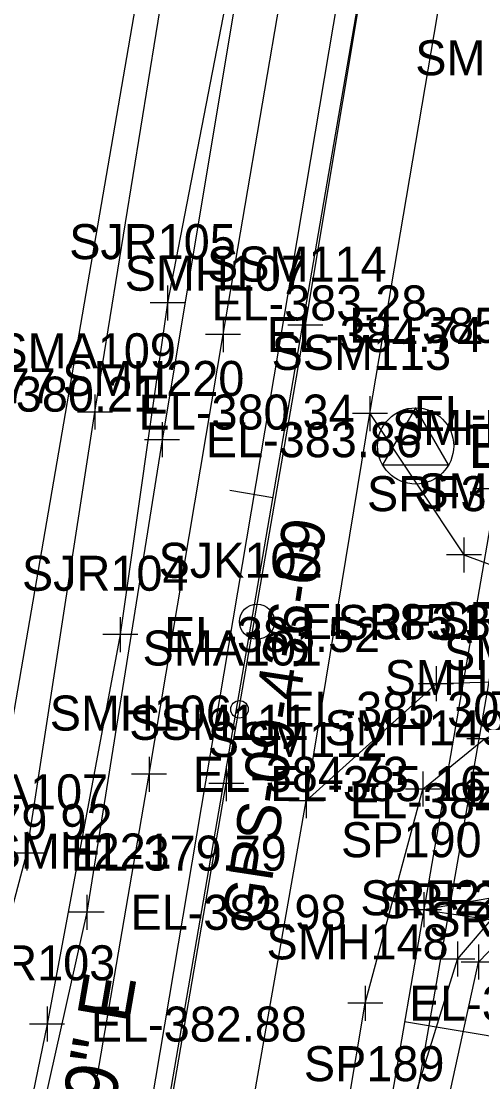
# Model space of a CAD drawing. Extents: x 1189978 to 1314812, y 571533 to 629339.
# Drawn here: x 1217440.8 to 1217493.5, y 620970.5 to 621091.6 of the extents above; entities that cross this region are included whole.
import ezdxf

# ---------------------------------------------------------------- set-up
doc = ezdxf.new("R2010")
doc.units = 0
for name, color, linetype in [('SURVEY - CENTERLINE - Preliminary', 7, 'Continuous'), ('SURVEY - CENTERLINE - Preliminary Text', 7, 'Continuous'), ('SURVEY - CONTROL - Points - Elevations', 7, 'Continuous'), ('SURVEY - CONTROL with Text', 7, 'Continuous'), ('SURVEY - DRAINAGE - Area Shapes', 7, 'Continuous'), ('SURVEY - DRAINAGE - Bridge Hydraulic Data with Text', 7, 'Continuous'), ('SURVEY - DTM - Breaklines', 7, 'Continuous'), ('SURVEY - DTM - Breaklines - Points - Elevations', 7, 'Continuous'), ('SURVEY - DTM - Breaklines - Points - Locators', 7, 'Continuous'), ('SURVEY - DTM - Breaklines - Points - Numbers', 7, 'Continuous'), ('SURVEY - DTM - Spot Points - Elevations', 7, 'Continuous'), ('SURVEY - DTM - Spot Points - Locators', 7, 'Continuous'), ('SURVEY - DTM - Spot Points - Point Numbers', 7, 'Continuous'), ('SURVEY - NON-TRANSPORTATION - Features', 7, 'Continuous'), ('SURVEY - NON-TRANSPORTATION - Features - Points - Elevations', 7, 'Continuous'), ('SURVEY - NON-TRANSPORTATION - Features - Points - Numbers', 7, 'Continuous'), ('SURVEY - PROPERTY - Property Lines', 7, 'Continuous'), ('SURVEY - PROPERTY - ROW Lines', 7, 'Continuous'), ('SURVEY - PROPERTY - ROW Lines - Points - Locators', 7, 'Continuous'), ('SURVEY - PROPERTY - ROW Lines - Points - Numbers', 7, 'Continuous'), ('SURVEY - PROPERTY - ROW Lines Text', 7, 'Continuous'), ('SURVEY - PROPERTY - Station and Offset Flags', 7, 'Continuous'), ('SURVEY - TRANSPORTATION - Features', 7, 'Continuous'), ('SURVEY - TRANSPORTATION - Features - Points - Locators', 7, 'Continuous'), ('SURVEY - TRANSPORTATION - Features - Points - Numbers', 7, 'Continuous'), ('SURVEY - TRANSPORTATION - Roads', 7, 'Continuous'), ('SURVEY - TRANSPORTATION - Roads - Points - Elevations', 7, 'Continuous'), ('SURVEY - TRANSPORTATION - Roads - Points - Locators', 7, 'Continuous'), ('SURVEY - TRANSPORTATION - Roads - Points - Numbers', 7, 'Continuous'), ('SURVEY - UTILITIES - Electric (Overhead) with Text', 7, 'Continuous'), ('SURVEY - VEGETATION - Features - Points - Elevations', 7, 'Continuous'), ('SURVEY - VEGETATION - Features - Points - Locators', 7, 'Continuous'), ('SURVEY - VEGETATION - Features - Points - Numbers', 7, 'Continuous'), ('SURVEY - VEGETATION - Features with Text', 7, 'Continuous')]:
    doc.layers.add(name, color=color, linetype=linetype)

msp = doc.modelspace()

# ---------------------------------------------------------------- linework, layer by layer
at = {"layer": 'SURVEY - CENTERLINE - Preliminary'}
msp.add_line((1217410.09, 620692.28), (1217501.58, 621222.71), dxfattribs=at)
msp.add_line((1217410.09, 620692.28), (1217501.58, 621222.71), dxfattribs=at)
at = {"layer": 'SURVEY - CENTERLINE - Preliminary Text'}
msp.add_line((1217469.58, 621037.19), (1217464.65, 621038.04), dxfattribs=at)
at = {"layer": 'SURVEY - CONTROL with Text'}
for p, q in [((1217485.89, 621047.46), (1217482.12, 621040.94)), ((1217489.65, 621040.94), (1217485.89, 621047.46)), ((1217485.89, 621043.11), (1217485.89, 621043.11)), ((1217482.12, 621040.94), (1217489.65, 621040.94))]:
    msp.add_line(p, q, dxfattribs=at)
msp.add_circle((1217485.89, 621043.11), 4.35, dxfattribs=at)
at = {"layer": 'SURVEY - DRAINAGE - Area Shapes'}
msp.add_line((1217415.87, 620731.68), (1218149.36, 625079.9), dxfattribs=at)
at = {"layer": 'SURVEY - DRAINAGE - Bridge Hydraulic Data with Text'}
msp.add_line((1217496.44, 621038.22), (1217492.44, 621038.22), dxfattribs=at)
at = {"layer": 'SURVEY - DTM - Breaklines'}
for points in [[(1217387.16, 620695.14), (1217397.48, 620747.65), (1217407.02, 620809.24), (1217418.75, 620878.96), (1217427.19, 620935.15), (1217426.68, 620940.89), (1217441.48, 620996.6), (1217449.24, 621046.98), (1217458, 621101.08), (1217460.79, 621140.2), (1217471.39, 621192.44), (1217489.7, 621292.1), (1217492.93, 621335.46), (1217504.86, 621384.61), (1217513.97, 621433.22), (1217517.91, 621473.83), (1217528.68, 621518.7), (1217534.78, 621566.14), (1217543.47, 621612.64), (1217549.89, 621643.65), (1217551.17, 621685.8), (1217565.36, 621705.38)], [(1217567.58, 621678.78), (1217566.65, 621676.81), (1217561.06, 621675.09), (1217559.37, 621666.41), (1217560.08, 621650.79), (1217551.98, 621602.78), (1217540.51, 621551.93), (1217533.57, 621500.33), (1217524.41, 621453.51), (1217516.18, 621399.79), (1217505.66, 621346.61), (1217497.91, 621291.92), (1217486.51, 621241.58), (1217479.66, 621189.93), (1217471.35, 621146.03), (1217465.62, 621095.91), (1217456.92, 621043.82), (1217448.31, 620989.84), (1217436.81, 620938.63)], [(1217418.06, 620739.44), (1217427.36, 620792.56), (1217436.72, 620845.05), (1217446.22, 620900.31), (1217455.61, 620954.21), (1217464.26, 621004.54), (1217473.29, 621056.89), (1217481.83, 621108.05), (1217491.34, 621163.83), (1217500.43, 621216.55), (1217508.98, 621267.02), (1217518.36, 621323.37), (1217527.29, 621375.81), (1217536.19, 621428.97), (1217544.91, 621481.66), (1217554.38, 621538.38), (1217563.54, 621592.41), (1217571.82, 621642.48), (1217577.37, 621677.13)], [(1217472.07, 620931.34), (1217480.14, 620979.46), (1217486.73, 621003.92), (1217493.75, 621009.65), (1217500.22, 621012.51), (1217505.41, 621014.24)], [(1217481.12, 620931.16), (1217482.16, 620956.91), (1217490.66, 620984.5), (1217504.49, 621000.62), (1217508.49, 621010.32)], [(1217483.62, 620930.86), (1217487.01, 620956.46), (1217493.09, 620984.16), (1217509.63, 621001.3)]]:
    msp.add_lwpolyline(points, dxfattribs=at)
at = {"layer": 'SURVEY - DTM - Breaklines - Points - Locators'}
for p, q in [((1217473.29, 621058.89), (1217473.29, 621054.89)), ((1217475.29, 621056.89), (1217471.29, 621056.89)), ((1217449.24, 621048.98), (1217449.24, 621044.98)), ((1217451.24, 621046.98), (1217447.24, 621046.98)), ((1217456.92, 621045.82), (1217456.92, 621041.82)), ((1217458.92, 621043.82), (1217454.92, 621043.82)), ((1217495.75, 621009.65), (1217491.75, 621009.65)), ((1217464.26, 621006.54), (1217464.26, 621002.54)), ((1217486.73, 621005.92), (1217486.73, 621001.92)), ((1217466.26, 621004.54), (1217462.26, 621004.54)), ((1217488.73, 621003.92), (1217484.73, 621003.92)), ((1217441.48, 620998.6), (1217441.48, 620994.6)), ((1217443.48, 620996.6), (1217439.48, 620996.6)), ((1217448.31, 620991.84), (1217448.31, 620987.84)), ((1217450.31, 620989.84), (1217446.31, 620989.84)), ((1217490.66, 620986.5), (1217490.66, 620982.5)), ((1217493.09, 620986.16), (1217493.09, 620982.16)), ((1217492.66, 620984.5), (1217488.66, 620984.5)), ((1217495.09, 620984.16), (1217491.09, 620984.16)), ((1217480.14, 620981.46), (1217480.14, 620977.46)), ((1217482.14, 620979.46), (1217478.14, 620979.46))]:
    msp.add_line(p, q, dxfattribs=at)
at = {"layer": 'SURVEY - DTM - Spot Points - Locators'}
msp.add_circle((1217465.77, 621013.03), 1, dxfattribs=at)
at = {"layer": 'SURVEY - NON-TRANSPORTATION - Features'}
msp.add_circle((1217467.76, 621023.05), 2, dxfattribs=at)
at = {"layer": 'SURVEY - PROPERTY - Property Lines'}
msp.add_line((1217486.83, 620990.13), (1218812.31, 620794.77), dxfattribs=at)
at = {"layer": 'SURVEY - PROPERTY - ROW Lines'}
for p, q in [((1217385.46, 620696.53), (1217476.94, 621226.96)), ((1217526.21, 621218.46), (1217486.83, 620990.13)), ((1217486.83, 620990.13), (1217482.42, 620964.55))]:
    msp.add_line(p, q, dxfattribs=at)
at = {"layer": 'SURVEY - PROPERTY - ROW Lines - Points - Locators'}
for p, q in [((1217486.83, 620992.13), (1217486.83, 620988.13)), ((1217488.83, 620990.13), (1217484.83, 620990.13))]:
    msp.add_line(p, q, dxfattribs=at)
at = {"layer": 'SURVEY - PROPERTY - ROW Lines Text'}
msp.add_lwpolyline([(1217714.69, 620938.77), (1217484.63, 620977.34)], dxfattribs=at)
at = {"layer": 'SURVEY - PROPERTY - Station and Offset Flags'}
msp.add_lwpolyline([(1217577.44, 621005.94), (1217486.83, 620990.13)], dxfattribs=at)
at = {"layer": 'SURVEY - TRANSPORTATION - Features'}
for points in [[(1217480.67, 621046.8), (1217491.41, 621030.66), (1217505.9, 621025.36), (1217530.42, 621026.78)], [(1217530.42, 621026.78), (1217530.16, 621006.83), (1217516.11, 621014.28), (1217499.82, 621016.27), (1217488.23, 621015.95), (1217473.39, 621002.58)]]:
    msp.add_lwpolyline(points, dxfattribs=at)
at = {"layer": 'SURVEY - TRANSPORTATION - Features - Points - Locators'}
for p, q in [((1217491.41, 621032.66), (1217491.41, 621028.66)), ((1217493.41, 621030.66), (1217489.41, 621030.66)), ((1217488.23, 621017.95), (1217488.23, 621013.95)), ((1217490.23, 621015.95), (1217486.23, 621015.95))]:
    msp.add_line(p, q, dxfattribs=at)
at = {"layer": 'SURVEY - TRANSPORTATION - Roads'}
for points in [[(1217409.51, 620742.51), (1217418.87, 620794.59), (1217428.1, 620847.79), (1217437.4, 620901.38), (1217446.45, 620953.25), (1217455.44, 621005.6), (1217463.89, 621055.84), (1217472.9, 621108.56), (1217482.31, 621162.33), (1217491.19, 621215.01), (1217500.52, 621270.57), (1217509.55, 621324.4), (1217518.06, 621374.09), (1217518.81, 621378.64), (1217527.27, 621430.43), (1217535.85, 621480.99), (1217545.48, 621538.85), (1217553.74, 621589.36), (1217562.47, 621641.97), (1217568.75, 621678.54), (1217567.58, 621678.78)], [(1217427.25, 620738.21), (1217436.59, 620791.34), (1217445.34, 620842.59), (1217455.15, 620898.88), (1217464.25, 620950.62), (1217473.39, 621002.58), (1217480.67, 621046.8), (1217490.83, 621106.73), (1217500.22, 621160.55), (1217509.53, 621215.72), (1217518.41, 621266.5), (1217527.5, 621321.85), (1217536.34, 621374.24), (1217563.48, 621537.92), (1217572.05, 621588.6), (1217580.58, 621640.89), (1217586, 621675.75), (1217587.38, 621675.54)]]:
    msp.add_lwpolyline(points, dxfattribs=at)
at = {"layer": 'SURVEY - TRANSPORTATION - Roads - Points - Locators'}
for p, q in [((1217463.89, 621057.84), (1217463.89, 621053.84)), ((1217465.89, 621055.84), (1217461.89, 621055.84)), ((1217480.67, 621048.8), (1217480.67, 621044.8)), ((1217482.67, 621046.8), (1217478.67, 621046.8)), ((1217455.44, 621007.6), (1217455.44, 621003.6)), ((1217457.44, 621005.6), (1217453.44, 621005.6)), ((1217473.39, 621004.58), (1217473.39, 621000.58)), ((1217475.39, 621002.58), (1217471.39, 621002.58))]:
    msp.add_line(p, q, dxfattribs=at)
at = {"layer": 'SURVEY - UTILITIES - Electric (Overhead) with Text'}
msp.add_lwpolyline([(1217806.14, 622777), (1217743.09, 622422.64), (1217688.2, 622113.29), (1217626.83, 621775.19), (1217569.14, 621442.23), (1217508.83, 621100.02), (1217448.24, 620751.9)], dxfattribs=at)
at = {"layer": 'SURVEY - VEGETATION - Features - Points - Locators'}
for p, q in [((1217457.55, 621061.45), (1217457.55, 621057.45)), ((1217459.55, 621059.45), (1217455.55, 621059.45)), ((1217452.15, 621023.57), (1217452.15, 621019.57)), ((1217454.15, 621021.57), (1217450.15, 621021.57)), ((1217443.78, 620979.07), (1217443.78, 620975.07)), ((1217445.78, 620977.07), (1217441.78, 620977.07))]:
    msp.add_line(p, q, dxfattribs=at)
at = {"layer": 'SURVEY - VEGETATION - Features with Text'}
msp.add_lwpolyline([(1217560.76, 621675.93), (1217556.7, 621644.18), (1217551.37, 621604.87), (1217540.8, 621553.12), (1217537.15, 621511.96), (1217530.13, 621471.54), (1217522.44, 621431.38), (1217515.9, 621389.36), (1217510.94, 621348.81), (1217502.94, 621307.06), (1217494.55, 621266.12), (1217486.37, 621220.88), (1217482.4, 621178.78), (1217475.75, 621141.85), (1217465.35, 621099.73), (1217457.55, 621059.45), (1217452.15, 621021.57), (1217443.78, 620977.07), (1217434.58, 620932.47)], dxfattribs=at)

# ---------------------------------------------------------------- texts
at = {"layer": 'SURVEY - CENTERLINE - Preliminary Text'}
msp.add_text('N 9%%d 47\' 09" E', height=6, rotation=80.2141, dxfattribs=at).set_placement((1217445.52, 620933.02))
at = {"layer": 'SURVEY - CONTROL - Points - Elevations'}
msp.add_text('EL-384.32', height=5, dxfattribs=at).set_placement((1217491.89, 621040.61))
at = {"layer": 'SURVEY - CONTROL with Text'}
msp.add_text('GPS-09-436-09', height=5, rotation=81.3035, dxfattribs=at).set_placement((1217468.68, 620988.09))
at = {"layer": 'SURVEY - DTM - Breaklines - Points - Elevations'}
for s, p in [('EL-385.33', (1217478.29, 621054.89)), ('EL-387.77', (1217420.07, 621047.98)), ('EL-380.21', (1217431.89, 621047.03)), ('EL-380.34', (1217454.24, 621044.98)), ('EL-383.86', (1217461.92, 621041.82)), ('EL-385.16', (1217469.26, 621002.54)), ('EL-383.35', (1217491.73, 621001.92)), ('EL-379.92', (1217426.57, 620998.19)), ('EL-379.79', (1217446.48, 620994.6)), ('EL-383.98', (1217453.31, 620987.84)), ('EL-382.76', (1217485.14, 620977.46))]:
    msp.add_text(s, height=4, dxfattribs=at).set_placement(p)
at = {"layer": 'SURVEY - DTM - Breaklines - Points - Numbers'}
for s, p in [('SMH156', (1217485.85, 621085.45)), ('SSM114', (1217462.06, 621061.89)), ('SMA109', (1217437.98, 621051.98)), ('SMH220', (1217445.51, 621048.82)), ('SMH155', (1217483.2, 621043.22)), ('SMH154', (1217486.09, 621035.97)), ('SMH151', (1217489.13, 621017.51)), ('SMH150', (1217482.34, 621014.65)), ('SSM111', (1217453.17, 621009.54)), ('SMH149', (1217475.48, 621008.92)), ('SMA107', (1217430.24, 621001.6)), ('SMH221', (1217437.22, 620994.84)), ('SRF271', (1217479.58, 620989.5)), ('SRF270', (1217481.68, 620989.16)), ('SRF269', (1217487.45, 620987.05)), ('SMH148', (1217468.85, 620984.46))]:
    msp.add_text(s, height=4, dxfattribs=at).set_placement(p)
at = {"layer": 'SURVEY - DTM - Spot Points - Elevations'}
msp.add_text('EL-385.30', height=4, dxfattribs=at).set_placement((1217470.77, 621011.03))
at = {"layer": 'SURVEY - DTM - Spot Points - Point Numbers'}
msp.add_text('SMA101', height=4, dxfattribs=at).set_placement((1217454.69, 621018.03))
at = {"layer": 'SURVEY - NON-TRANSPORTATION - Features - Points - Elevations'}
msp.add_text('EL-385.30', height=4, dxfattribs=at).set_placement((1217472.76, 621021.05))
at = {"layer": 'SURVEY - NON-TRANSPORTATION - Features - Points - Numbers'}
msp.add_text('SJK102', height=4, dxfattribs=at).set_placement((1217456.52, 621028.05))
at = {"layer": 'SURVEY - PROPERTY - ROW Lines - Points - Numbers'}
for s, p in [('SP190', (1217477.37, 620996.13)), ('SP189', (1217473.12, 620970.55))]:
    msp.add_text(s, height=4, dxfattribs=at).set_placement(p)
at = {"layer": 'SURVEY - TRANSPORTATION - Features - Points - Numbers'}
for s, p in [('SRF311', (1217480.33, 621035.66)), ('SRF317', (1217476.99, 621020.95)), ('SRF316', (1217488.47, 621021.27))]:
    msp.add_text(s, height=4, dxfattribs=at).set_placement(p)
at = {"layer": 'SURVEY - TRANSPORTATION - Roads - Points - Elevations'}
for s, p in [('EL-384.74', (1217468.89, 621053.84)), ('EL-385.12', (1217485.67, 621044.8)), ('EL-384.73', (1217460.44, 621003.6)), ('EL-384.92', (1217478.39, 621000.58))]:
    msp.add_text(s, height=4, dxfattribs=at).set_placement(p)
at = {"layer": 'SURVEY - TRANSPORTATION - Roads - Points - Numbers'}
for s, p in [('SMH107', (1217452.65, 621060.84)), ('SSM113', (1217469.43, 621051.8)), ('SMH106', (1217444.09, 621010.6)), ('SSM112', (1217462.15, 621007.58))]:
    msp.add_text(s, height=4, dxfattribs=at).set_placement(p)
at = {"layer": 'SURVEY - VEGETATION - Features - Points - Elevations'}
for s, p in [('EL-383.28', (1217462.55, 621057.45)), ('EL-383.52', (1217457.15, 621019.57)), ('EL-382.88', (1217448.78, 620975.07))]:
    msp.add_text(s, height=4, dxfattribs=at).set_placement(p)
at = {"layer": 'SURVEY - VEGETATION - Features - Points - Numbers'}
for s, p in [('SJR105', (1217446.31, 621064.45)), ('SJR104', (1217440.91, 621026.57)), ('SJR103', (1217432.54, 620982.07))]:
    msp.add_text(s, height=4, dxfattribs=at).set_placement(p)

doc.saveas('drawing.dxf')
